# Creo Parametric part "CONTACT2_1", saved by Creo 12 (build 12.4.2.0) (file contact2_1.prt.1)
Units: Custom; MM, KILOGRAM, SECS

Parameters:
  PTC_WM_ITERATION = "0"
  PTC_WM_VERSION = "-.0"
  PTC_WM_LIFECYCLE_STATE = "In Work"
  PTC_WM_LIFECYCLE = "MO_CADDocument"
  PTC_WM_CREATED_BY = "Maximilian Roepper (Z0017RMS: MO)"
  PTC_WM_CREATED_ON = "18-Sep-26 11:36:42 AM"
  PTC_WM_MODIFIED_BY = "Maximilian Roepper (Z0017RMS: MO)"
  PTC_WM_MODIFIED_ON = "18-Sep-26 11:36:46 AM"
  PDMLINKNUMBER = "PDM000071455348"
  PTC_WM_NAME = "contact2_1.prt"
  PTC_WM_NUMBER = "PDM000071455348"

Other parameters: WEIGHT, WEIGHT_FACTOR, WEIGHT_ADD, _MASS_TEMP, _DIFF_TEMP, MC_ERRORS, SUPPLIER

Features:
  1. coordinate system
  2. datum plane "PRT_YZ"
  3. datum plane "PRT_XY"
  4. datum plane "PRT_XZ"
  5. coordinate system
  6. datum axis
  7. datum axis
  8. datum axis
  9. coordinate system
  10. imported feature

Other named items: PRT, SIEMENS_MO, DRW_VIEW_ORG, PRT_X, PRT_Y, PRT_Z, CS0, ROUGH_GROB

Layers: 00_STD_CSYS-KSYS, 01_STD_PLANES-EBENEN, 02_STD_AXES-ACHSEN, 03_STD_CSYS-KSYS, 24_IMPORT_FEAT-IMPORT_KE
